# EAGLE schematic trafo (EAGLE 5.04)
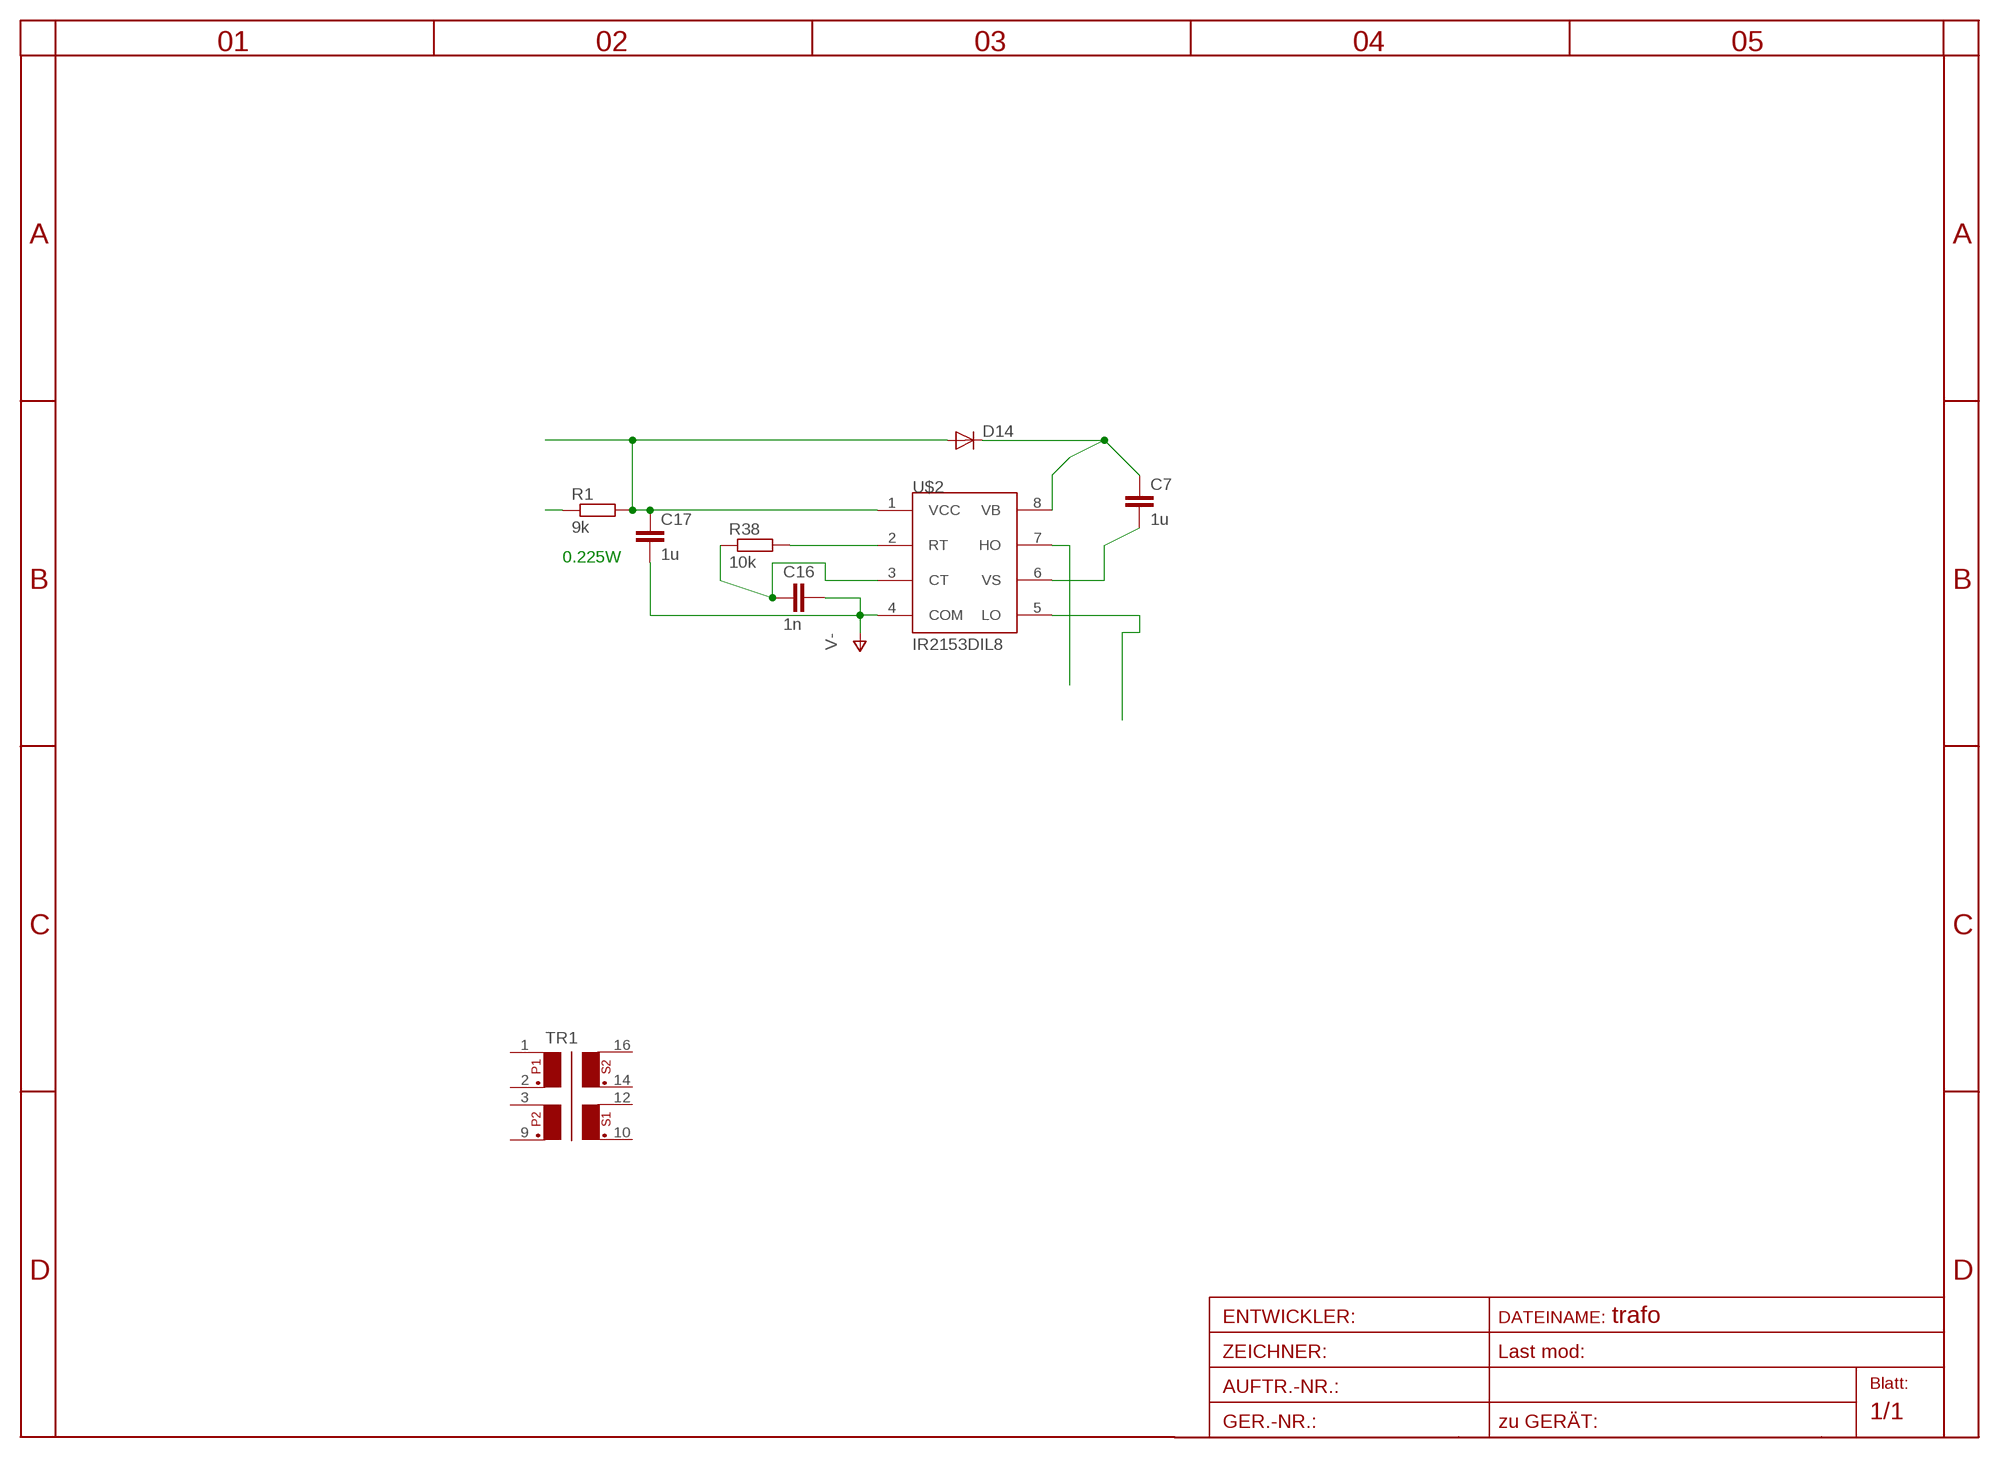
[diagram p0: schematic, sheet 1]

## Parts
C7  1u  C-EU050-025X075  [C050-025X075]
C16  1n  C-EU025-050X050  [C025-050X050]
C17  1u  C-EU050-030X075  [C050-030X075]
D14  DIODE-D-5  [D-5]
R1  9k  R-EU_0204/2V  [0204V]
R38  10k  R-EU_0204/2V  [0204V]
TR1  FL52EP16CONR  [EP16]
U$2  IR2153DIL8  [DIL08]

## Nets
CT: C16.1 R38.1 U$2.3(CT)
GATE: U$2.7(HO)
N$1: R1.1
N$6: C7.2 U$2.6(VS)
N$33: U$2.5(LO)
N$40: R38.2 U$2.2(RT)
V-: C16.2 C17.2 U$2.4(COM)
VB: C7.1 D14.C U$2.8(VB)
VCC: C17.1 D14.A R1.2 U$2.1(VCC)
Unconnected: TR1.1 TR1.2 TR1.3 TR1.9 TR1.10 TR1.12 TR1.14 TR1.16

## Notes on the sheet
- 0.225W

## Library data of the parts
C7 C16 C17 = rcl-2:C-EU: CAPACITOR, European symbol
D14 = diode-1:DIODE-: DIODE
R1 R38 = rcl-2:R-EU_: RESISTOR, European symbol
TR1 = trafo:FL52: TRANSFORMER 2 primary winding, 2 secondary windings, mounting holes BLOCK
U$2 = irf-2:IR2153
